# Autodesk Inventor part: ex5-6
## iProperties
Shininess: 64.0
Length Units: 11272
Angle Units: 11279
Time Units: 11290
Mass Units: 11286
Length Display Precision: 3
Angle Display Precision: 2
Compacted: True
Part Number: ex5-6
Document SubType Name: Modeling
Created: 2002-09
Designer: Elise Moss
Density: 0.0
Volumn: 0.0
Area: 0.0
PropertySet Name: Model Information
Control State: 0
Master: False
Checked Out: False
Author: Elise Moss
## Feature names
1. Revolution1
2. Hole1
3. Shell1
4. Loft1
5. Sweep1
